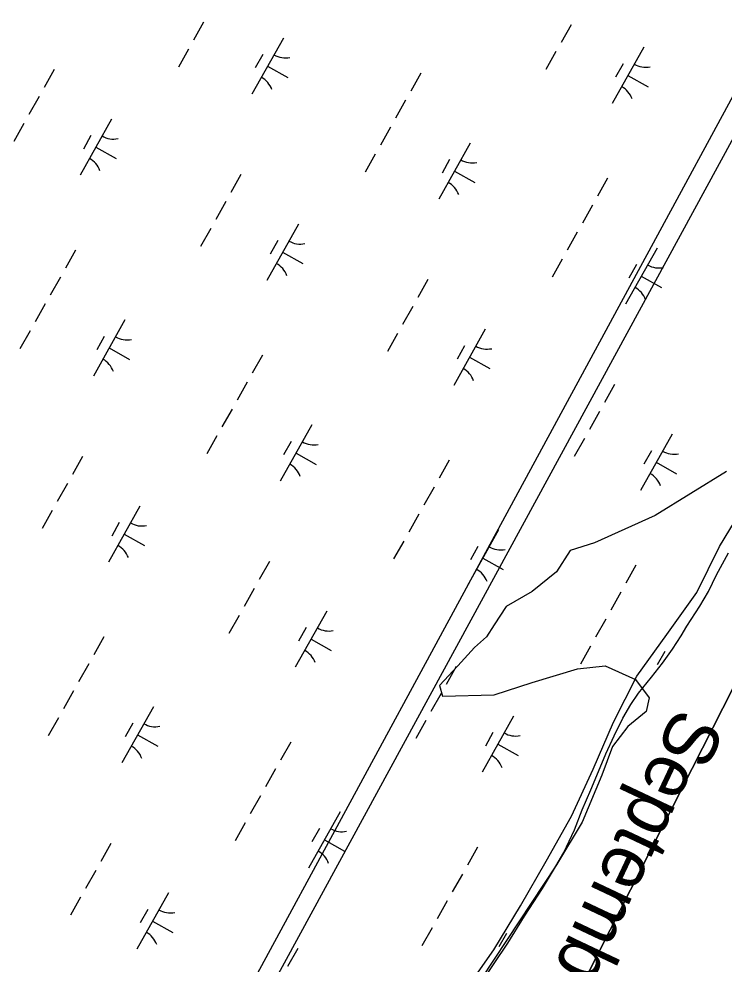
# Model space of a CAD drawing. Extents: x 3913936 to 3933962, y 195330 to 217741.
# Drawn here: x 3925601 to 3926148, y 208772 to 209506 of the extents above; entities that cross this region are included whole.
import ezdxf

# ---------------------------------------------------------------- set-up
doc = ezdxf.new("R2010")
doc.units = 0
for name, color, linetype in [('V-RIVR-EDGE', 7, 'Continuous'), ('V-RIVR-IDEN', 7, 'Continuous'), ('V-RRAP-FSHR', 7, 'Continuous'), ('V-TOPO-DPTH', 7, 'Continuous'), ('V-TOPO-MINR', 7, 'Continuous'), ('V-UTIL-LINE', 7, 'Continuous'), ('V-WETL-SWMP', 7, 'Continuous')]:
    doc.layers.add(name, color=color, linetype=linetype)

msp = doc.modelspace()

# ---------------------------------------------------------------- linework, layer by layer
at = {"layer": 'V-RIVR-EDGE'}
msp.add_lwpolyline([(3926150.08, 209154.75), (3926094.68, 209120.57), (3926047.54, 209099.35), (3926028.68, 209093.46), (3926018.07, 209076.96), (3925999.21, 209061.63), (3925979.17, 209049.85), (3925969.74, 209035.7), (3925963.85, 209026.27), (3925954.42, 209018.02), (3925941.45, 209003.88), (3925927.31, 208988.55), (3925929.66, 208980.3), (3925969.74, 208981.48), (3925999.21, 208990.91), (3926034.57, 209001.52), (3926055.79, 209003.88), (3926079.36, 208993.27), (3926089.97, 208979.12), (3926087.61, 208968.52), (3926073.47, 208956.73), (3926061.68, 208941.41), (3926053.43, 208919.01), (3926038.11, 208882.47), (3926018.07, 208849.47), (3925930.84, 208717.45)], dxfattribs=at)
at = {"layer": 'V-RRAP-FSHR'}
msp.add_lwpolyline([(3925946.53, 208750.7), (3925969.53, 208783.42), (3925990.2, 208817.63), (3926010.19, 208852.37), (3926029.68, 208887.2), (3926046.72, 208923.69), (3926062.46, 208960.17), (3926080.4, 208995.77), (3926103.77, 209028.23), (3926127.14, 209060.69), (3926144.53, 209096.38), (3926165.14, 209130.13)], dxfattribs=at)
at = {"layer": 'V-TOPO-DPTH'}
msp.add_lwpolyline([(3925446.13, 207592.35), (3926234.96, 209143.49), (3926242.01, 209157.51), (3926248.98, 209171.58), (3926255.82, 209185.71), (3926262.57, 209199.88), (3926272.29, 209220.51), (3926274.13, 209224.39), (3926275.99, 209228.27), (3926277.87, 209232.15), (3926279.76, 209236.01), (3926283.56, 209243.73), (3926521.82, 209162.31)], dxfattribs=at)
at = {"layer": 'V-TOPO-MINR'}
msp.add_lwpolyline([(3926283.56, 209243.73), (3926279.76, 209236.01), (3926277.87, 209232.15), (3926275.99, 209228.27), (3926274.13, 209224.39), (3926272.29, 209220.51), (3926262.57, 209199.88), (3926255.82, 209185.71), (3926248.98, 209171.58), (3926242.01, 209157.51), (3926234.96, 209143.49), (3925446.13, 207592.35)], dxfattribs=at)
at = {"layer": 'V-UTIL-LINE'}
for points in [[(3928315.82, 212388.13), (3926944.7, 210748.94), (3926592.74, 210251.47), (3926408.93, 209914.99), (3925628.64, 208474.44), (3925139.98, 207727.42), (3924555.96, 206253.65), (3924055.82, 204771.45), (3923484.9, 203858.52), (3922256.01, 202262.65), (3921816.4, 201905.57), (3920704.84, 200345.08), (3920462.44, 200062.72)], [(3928328.32, 212380.93), (3926784.14, 210502.92), (3926424.72, 209908.68), (3925640.45, 208467.64), (3924952.2, 207329.25), (3923971.74, 204752.16), (3923252.9, 203563.68), (3921560.17, 201558.84), (3920397.87, 200112.86)]]:
    msp.add_lwpolyline(points, dxfattribs=at)
at = {"layer": 'V-WETL-SWMP'}
for p, q in [((3925744.3, 209503.46), (3925736.46, 209489.51)), ((3926029.49, 209501.45), (3926021.65, 209487.5)), ((3925806.23, 209491.1), (3925781.73, 209447.52)), ((3926085.83, 209483.88), (3926061.33, 209440.3)), ((3925732.54, 209482.53), (3925724.7, 209468.59)), ((3925790.19, 209478.32), (3925784.31, 209467.86)), ((3926017.73, 209480.53), (3926009.89, 209466.58)), ((3925793.98, 209469.31), (3925809.67, 209460.49)), ((3926069.79, 209471.1), (3926063.91, 209460.64)), ((3925628.28, 209466.63), (3925620.44, 209452.68)), ((3925912.82, 209463.79), (3925904.98, 209449.84)), ((3926073.58, 209462.09), (3926089.27, 209453.27)), ((3925616.52, 209445.71), (3925608.68, 209431.76)), ((3925901.06, 209442.87), (3925893.22, 209428.92)), ((3925672.86, 209428.14), (3925648.36, 209384.56)), ((3925604.76, 209424.79), (3925596.92, 209410.84)), ((3925889.3, 209421.95), (3925881.46, 209408)), ((3925656.82, 209415.36), (3925650.94, 209404.9)), ((3925660.61, 209406.35), (3925676.3, 209397.53)), ((3925951.23, 209409.59), (3925926.73, 209366.01)), ((3925877.54, 209401.02), (3925869.7, 209387.08)), ((3925935.19, 209396.81), (3925929.31, 209386.35)), ((3925773.28, 209385.12), (3925765.44, 209371.17)), ((3925938.98, 209387.8), (3925954.67, 209378.98)), ((3926057.82, 209382.28), (3926049.98, 209368.33)), ((3925761.52, 209364.2), (3925753.68, 209350.25)), ((3926046.06, 209361.36), (3926038.22, 209347.41)), ((3925817.86, 209346.63), (3925793.36, 209303.05)), ((3925749.76, 209343.28), (3925741.92, 209329.33)), ((3926034.3, 209340.44), (3926026.46, 209326.49)), ((3925801.82, 209333.85), (3925795.94, 209323.39)), ((3925644.85, 209326.54), (3925637.01, 209312.59)), ((3925805.61, 209324.84), (3925821.3, 209316.02)), ((3926096.22, 209328.08), (3926071.72, 209284.5)), ((3926022.54, 209319.52), (3926014.7, 209305.57)), ((3926080.19, 209315.3), (3926074.31, 209304.84)), ((3925633.09, 209305.62), (3925625.25, 209291.67)), ((3925918.28, 209303.61), (3925910.44, 209289.66)), ((3926083.97, 209306.29), (3926099.67, 209297.47)), ((3925621.33, 209284.7), (3925613.49, 209270.75)), ((3925906.52, 209282.69), (3925898.68, 209268.74)), ((3925683.26, 209272.34), (3925658.75, 209228.76)), ((3925609.57, 209263.78), (3925601.73, 209249.83)), ((3925962.86, 209265.12), (3925938.36, 209221.54)), ((3925667.22, 209259.56), (3925661.34, 209249.1)), ((3925894.76, 209261.77), (3925886.92, 209247.82)), ((3925671.01, 209250.55), (3925686.7, 209241.73)), ((3925946.82, 209252.34), (3925940.94, 209241.88)), ((3925789.85, 209245.03), (3925782.01, 209231.08)), ((3925950.61, 209243.33), (3925966.3, 209234.51)), ((3925778.09, 209224.11), (3925770.25, 209210.16)), ((3926063.28, 209222.1), (3926055.44, 209208.15)), ((3925766.33, 209203.19), (3925758.49, 209189.24)), ((3926051.52, 209201.18), (3926043.68, 209187.23)), ((3925828.25, 209190.83), (3925803.75, 209147.25)), ((3926107.85, 209183.62), (3926083.35, 209140.03)), ((3925754.57, 209182.27), (3925746.73, 209168.32)), ((3925812.22, 209178.05), (3925806.34, 209167.59)), ((3926039.76, 209180.26), (3926031.92, 209166.31)), ((3925816, 209169.04), (3925831.69, 209160.22)), ((3926091.82, 209170.83), (3926085.94, 209160.37)), ((3925650.31, 209166.36), (3925642.47, 209152.41)), ((3925934.85, 209163.52), (3925927.01, 209149.57)), ((3926095.6, 209161.82), (3926111.29, 209153)), ((3925638.55, 209145.44), (3925630.71, 209131.49)), ((3925923.08, 209142.6), (3925915.24, 209128.65)), ((3925626.79, 209124.52), (3925618.95, 209110.57)), ((3925694.89, 209127.87), (3925670.38, 209084.29)), ((3925911.32, 209121.68), (3925903.48, 209107.73)), ((3925678.85, 209115.09), (3925672.97, 209104.63)), ((3925682.63, 209106.08), (3925698.33, 209097.26)), ((3925973.25, 209109.33), (3925948.75, 209065.74)), ((3925899.56, 209100.76), (3925891.72, 209086.81)), ((3925957.22, 209096.54), (3925951.34, 209086.08)), ((3926142.3, 209074.5), (3926151.55, 209091.58)), ((3925795.31, 209084.85), (3925787.47, 209070.9)), ((3925961, 209087.53), (3925976.69, 209078.71)), ((3926079.84, 209082.01), (3926072, 209068.06)), ((3926136.15, 209061.63), (3926142.3, 209074.5)), ((3925783.55, 209063.93), (3925775.71, 209049.98)), ((3926068.08, 209061.09), (3926060.24, 209047.14)), ((3926129.46, 209050.07), (3926136.15, 209061.63)), ((3925839.88, 209046.37), (3925815.38, 209002.78)), ((3926119.32, 209034.55), (3926129.46, 209050.07)), ((3925771.79, 209043.01), (3925763.95, 209029.06)), ((3926056.32, 209040.17), (3926048.48, 209026.22)), ((3925823.85, 209033.58), (3925817.97, 209023.12)), ((3926114.95, 209027.19), (3926119.32, 209034.55)), ((3925666.87, 209026.27), (3925659.03, 209012.32)), ((3925827.63, 209024.57), (3925843.32, 209015.75)), ((3926108.25, 209016.93), (3926114.95, 209027.19)), ((3926044.56, 209019.25), (3926036.72, 209005.3)), ((3926102.21, 209015.03), (3926096.33, 209004.57)), ((3926100.51, 209005.88), (3926108.25, 209016.93)), ((3925655.11, 209005.35), (3925647.27, 208991.4)), ((3925940.31, 209003.34), (3925932.46, 208989.39)), ((3926091.98, 208995.08), (3926100.51, 209005.88)), ((3926081.91, 208982.7), (3926091.98, 208995.08)), ((3925643.35, 208984.43), (3925635.51, 208970.48)), ((3925928.54, 208982.42), (3925920.7, 208968.47)), ((3926075.71, 208973.76), (3926081.91, 208982.7)), ((3925705.28, 208972.08), (3925680.78, 208928.49)), ((3926069.54, 208963.25), (3926075.71, 208973.76)), ((3925631.59, 208963.51), (3925623.75, 208949.56)), ((3925984.88, 208964.86), (3925960.38, 208921.27)), ((3926062.87, 208949.59), (3926069.54, 208963.25)), ((3925689.24, 208959.29), (3925683.36, 208948.83)), ((3925916.78, 208961.5), (3925908.94, 208947.55)), ((3925693.03, 208950.28), (3925708.72, 208941.46)), ((3925968.85, 208952.07), (3925962.97, 208941.61)), ((3926056.47, 208935.68), (3926062.87, 208949.59)), ((3925811.87, 208944.76), (3925804.03, 208930.81)), ((3925972.63, 208943.06), (3925988.32, 208934.24)), ((3926050.85, 208921.77), (3926056.47, 208935.68)), ((3925800.11, 208923.84), (3925792.27, 208909.89)), ((3926044.71, 208907.6), (3926050.85, 208921.77)), ((3926038.06, 208892.12), (3926044.71, 208907.6)), ((3925788.35, 208902.92), (3925780.51, 208888.97)), ((3925850.28, 208890.57), (3925825.78, 208846.98)), ((3926032.19, 208876.64), (3926038.06, 208892.12)), ((3925776.59, 208882), (3925768.75, 208868.05)), ((3925834.24, 208877.78), (3925828.36, 208867.32)), ((3926023.73, 208859.05), (3926032.19, 208876.64)), ((3925838.03, 208868.77), (3925853.72, 208859.95)), ((3925672.33, 208866.09), (3925664.49, 208852.14)), ((3925956.87, 208863.25), (3925949.03, 208849.3)), ((3926015.75, 208845.38), (3926023.73, 208859.05)), ((3925660.57, 208845.17), (3925652.73, 208831.22)), ((3925945.11, 208842.33), (3925937.27, 208828.38)), ((3926007.26, 208831.19), (3926015.75, 208845.38)), ((3925993.35, 208809.63), (3926007.26, 208831.19)), ((3925648.81, 208824.25), (3925640.97, 208810.3)), ((3925716.91, 208827.61), (3925692.41, 208784.02)), ((3925933.35, 208821.41), (3925925.51, 208807.46)), ((3925700.87, 208814.82), (3925694.99, 208804.36)), ((3925980.48, 208788.6), (3925993.35, 208809.63)), ((3925704.66, 208805.81), (3925720.35, 208796.99)), ((3925921.59, 208800.49), (3925913.75, 208786.54)), ((3925979.24, 208796.28), (3925973.36, 208785.81)), ((3925939.23, 208727.57), (3925980.48, 208788.6)), ((3925817.33, 208784.58), (3925809.49, 208770.63))]:
    msp.add_line(p, q, dxfattribs=at)
for centre, start, end in [((3925807.72, 209493.27), 239.88608, 281.42974), ((3926087.32, 209486.05), 239.88608, 281.42974), ((3925780.65, 209445.12), 19.88608, 61.42973), ((3926060.25, 209437.9), 19.88608, 61.42973), ((3925674.35, 209430.31), 239.88608, 281.42974), ((3925647.28, 209382.16), 19.88608, 61.42973), ((3925952.72, 209411.76), 239.88608, 281.42974), ((3925925.65, 209363.61), 19.88608, 61.42973), ((3925819.35, 209348.8), 239.88608, 281.42974), ((3925792.28, 209300.65), 19.88608, 61.42973), ((3926097.72, 209330.25), 239.88608, 281.42974), ((3926070.65, 209282.1), 19.88608, 61.42973), ((3925684.75, 209274.51), 239.88608, 281.42974), ((3925964.35, 209267.29), 239.88608, 281.42974), ((3925657.68, 209226.36), 19.88608, 61.42973), ((3925937.28, 209219.14), 19.88608, 61.42973), ((3925829.75, 209193), 239.88608, 281.42974), ((3926109.35, 209185.78), 239.88608, 281.42974), ((3925802.67, 209144.85), 19.88608, 61.42973), ((3926082.28, 209137.63), 19.88608, 61.42973), ((3925696.38, 209130.04), 239.88608, 281.42974), ((3925669.31, 209081.89), 19.88608, 61.42973), ((3925974.74, 209111.49), 239.88608, 281.42974), ((3925947.67, 209063.34), 19.88608, 61.42973), ((3925841.38, 209048.53), 239.88608, 281.42974), ((3925814.3, 209000.38), 19.88608, 61.42973), ((3925706.77, 208974.24), 239.88608, 281.42974), ((3925986.37, 208967.03), 239.88608, 281.42974), ((3925679.7, 208926.09), 19.88608, 61.42973), ((3925959.3, 208918.87), 19.88608, 61.42973), ((3925851.77, 208892.74), 239.88608, 281.42974), ((3925824.7, 208844.58), 19.88608, 61.42973), ((3925718.4, 208829.78), 239.88608, 281.42974), ((3925691.33, 208781.62), 19.88608, 61.42973)]:
    msp.add_arc(centre, 17.62, start, end, dxfattribs=at)

# ---------------------------------------------------------------- texts
at = {"layer": 'V-RIVR-IDEN'}
msp.add_text('September', height=42, rotation=244.71523, dxfattribs=at).set_placement((3926111.61, 208973.04))

doc.saveas('drawing.dxf')
